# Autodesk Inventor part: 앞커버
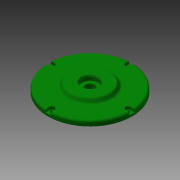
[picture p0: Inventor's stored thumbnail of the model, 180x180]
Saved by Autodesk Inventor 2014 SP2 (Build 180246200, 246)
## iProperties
Created: 2016-11
Part Number: 앞커버
Material: 알루미늄 6061
Document SubType Name: Modeling
Designer: mduedu
Density: 2.71 g/cm^3
Mass: 394.828 g
Surface Area: 366.341 cm^2
Volume: 145.693 cm^3
Appearance: 진녹색
Author: mduedu
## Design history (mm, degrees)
sketch "스케치1"
  geometry: L1 (22, -12.5)-(22, -30); L2 (22, -30)-(16, -33.464); L3 (16, -33.464)-(16, -65); L4 (16, -65)-(8, -65); L5 (8, -65)-(8, -53); L6 (8, -53)-(0, -53); L7 (0, -53)-(0, -14); L8 (0, 0)-(22, 0); L9 (8, -14)-(8, -7); L10 (8, -7)-(14.5, -7); L11 (14.5, -7)-(14.5, -12.5); L12 (0, -14)-(8, -14); L13 (14.5, -12.5)-(22, -12.5)
  constraints: 26 end point, 8 parallel, 3 perpendicular, 2 horizontal, 2 vertical alignment, 1 collinear
  dimensions: "d0" = 8 distance of L5.end L6.end; "d2" = 8 distance of L3.end L4.end; "d3" = 6 distance between parallel lines of L1 L3; "d4" = 120 deg angle of L3 L2; "d5" = 7.5 distance of L11.end L1.start; "d6" = 60 diameter of L1.end L8; "d7" = 14 diameter of L10 L8; "d8" = 28 diameter of L12 L8; "d9" = 25 diameter of L13 L8; "d10" = 106 diameter of L6 L8; "d11" = 130 diameter of L4 L8
revolve "회전1" sketch "스케치1" stored, may be unused: angle "d12" = 90 deg
fillet "모깎기1" dims "d13" = 0.3
fillet "모깎기2" dims "d14" = 3
chamfer "모따기1" distance "d15" = 1; stored, may be unused: second distance "d16" = 2, angle "d17" = 45 deg
fillet "모깎기3" dims "d18" = 0.3
chamfer "모따기2" distance "d36" = 2; stored, may be unused: second distance "d37" = 2, angle "d38" = 30 deg
sketch "스케치3"
  geometry: C1 r 65 at (0, 0) reference; A1 r 59 centre (0, 0) between (0, 59) and (59, 0); 2 further points
  constraints: 4 point on circle, 2 horizontal alignment, 2 vertical alignment, 1 centre point, 1 coincident
  dimensions: "d33" = 118 diameter of A1
sketch "스케치4"
  geometry: 4 further points
  constraints: 4 other
hole "구멍2" sketch "스케치4" at (0, 59), (-59, 0), (59, 0), (0, -59) diameter "d39" = 4.5; stored, may be unused: countersink angle "d43" = 90 deg, drill point angle "d45" = 0 deg; dims "d40" = 6, "d41" = 8, "d42" = 4.6, "d44" = 8
sketch "스케치6"
  geometry: L1 (-4, 5.877)-(-4, 0); L2 (4, 5.877)-(4, 0); A1 r 4 centre (0, 0) between (-2.712, 2.941) and (2.712, 2.941) reference; A2 r 65 centre (0, -59) between (-4, 5.877) and (4, 5.877) reference; 1 further point
  constraints: 4 end point, 4 point on circle, 2 tangent, 2 vertical
extrude "돌출2" cut sketch "스케치6" stored distance "d51" = 10; taper "d52" = 0 deg
fillet "모깎기5" dims "d56" = 0.3
fillet "모깎기6" dims "d57" = 0.3
sketch "스케치5"
  geometry: C1 r 22 at (0, 0); C2 r 45 at (0, 0); 1 further point
  constraints: 2 centre point, 2 coincident
  dimensions: "d46" = 44 diameter of C1; "d47" = 90 diameter of C2
extrude "돌출1" cut sketch "스케치5" distance "d48" = 8; taper "d49" = 0 deg
fillet "모깎기4" dims "d50" = 3
node "솔리드1"
pattern_circular "원형 패턴1" dims angle "d54" = 360 deg
pattern_circular "원형 패턴2" dims angle "d59" = 360 deg
pattern_circular "원형 패턴3" dims angle "d62" = 360 deg
